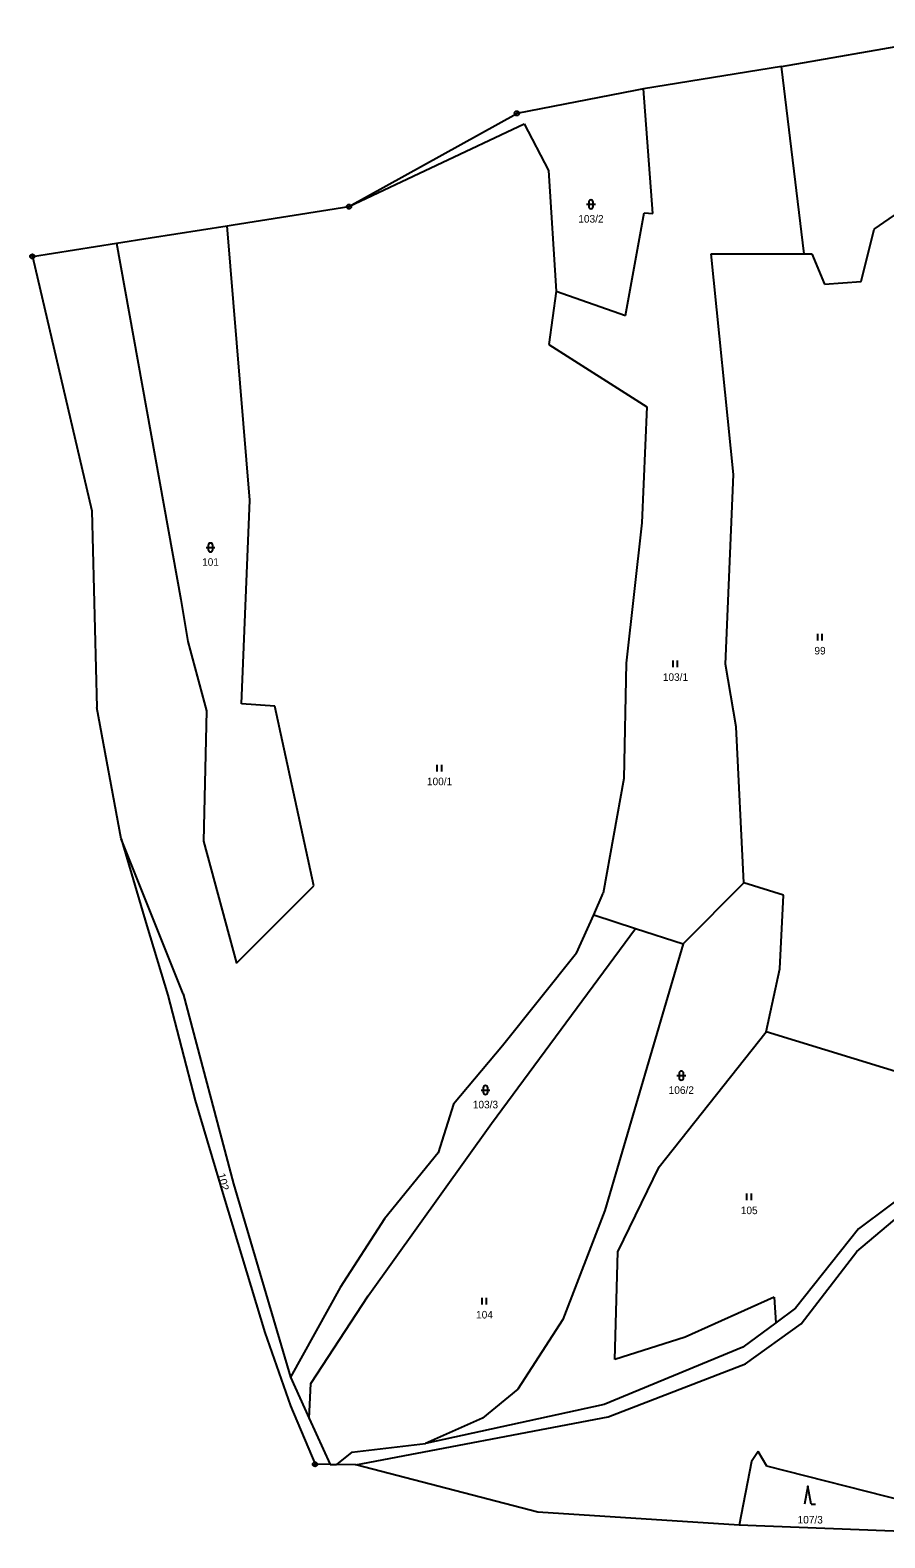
# Model space of a CAD drawing. Extents: x -601877 to -599786, y -1122905 to -1121218.
# Drawn here: x -601877.1 to -601684.6, y -1122131.2 to -1121791.7 of the extents above; entities that cross this region are included whole.
import ezdxf
from ezdxf.enums import TextEntityAlignment as Align

# ---------------------------------------------------------------- set-up
doc = ezdxf.new("R2010")
doc.units = 0
doc.header["$LTSCALE"] = 0.68
for name, color, linetype, lineweight in [('1', 7, 'Continuous', 25), ('3', 7, 'Continuous', 25), ('8', 7, 'Continuous', 25)]:
    doc.layers.add(name, color=color, linetype=linetype, lineweight=lineweight)
doc.layers.add('2', color=7, linetype='Continuous')

msp = doc.modelspace()

# ---------------------------------------------------------------- linework, layer by layer
at = {"layer": '1'}
for p, q in [((-601707.88, -1121799.89), (-601660.68, -1121791.7)), ((-601707.88, -1121799.89), (-601738.97, -1121804.94)), ((-601702.78, -1121842.1), (-601707.88, -1121799.89)), ((-601740.83, -1121805.3), (-601767.46, -1121810.44)), ((-601738.97, -1121804.94), (-601740.83, -1121805.3)), ((-601736.8, -1121832.96), (-601738.97, -1121804.94)), ((-601805.27, -1121831.44), (-601767.46, -1121810.44)), ((-601686.97, -1121836.54), (-601649.03, -1121810.29)), ((-601805.27, -1121831.44), (-601765.84, -1121812.82)), ((-601765.84, -1121812.82), (-601760.34, -1121823.28)), ((-601760.34, -1121823.28), (-601758.58, -1121850.46)), ((-601831.32, -1121835.53), (-601805.27, -1121831.44)), ((-601742.96, -1121855.97), (-601738.78, -1121832.85)), ((-601738.78, -1121832.85), (-601736.8, -1121832.96)), ((-601827.61, -1121897.52), (-601832.71, -1121835.75)), ((-601689.89, -1121848.32), (-601686.97, -1121836.54)), ((-601876.57, -1121842.65), (-601857.64, -1121839.67)), ((-601857.64, -1121839.67), (-601850.06, -1121838.48)), ((-601857.64, -1121839.67), (-601843.1, -1121919.91)), ((-601876.57, -1121842.65), (-601863.21, -1121899.96)), ((-601723.71, -1121842.04), (-601702.78, -1121842.1)), ((-601718.65, -1121891.74), (-601723.71, -1121842.04)), ((-601702.78, -1121842.1), (-601701, -1121842.1)), ((-601701, -1121842.1), (-601698.19, -1121848.92)), ((-601758.58, -1121850.46), (-601760.23, -1121862.46)), ((-601758.58, -1121850.46), (-601742.96, -1121855.97)), ((-601698.19, -1121848.92), (-601689.89, -1121848.32)), ((-601760.23, -1121862.46), (-601738.16, -1121876.51)), ((-601738.16, -1121876.51), (-601739.33, -1121902.63)), ((-601720.47, -1121934.44), (-601718.65, -1121891.74)), ((-601829.49, -1121943.36), (-601827.61, -1121897.52)), ((-601863.21, -1121899.96), (-601862.08, -1121944.21)), ((-601739.33, -1121902.63), (-601742.85, -1121934.22)), ((-601843.1, -1121919.91), (-601841.56, -1121929.38)), ((-601841.56, -1121929.38), (-601837.37, -1121944.96)), ((-601742.85, -1121934.22), (-601743.4, -1121960.2)), ((-601718.1, -1121948.58), (-601720.47, -1121934.44)), ((-601856.55, -1121973.77), (-601862.08, -1121944.21)), ((-601837.37, -1121944.96), (-601838.04, -1121974.28)), ((-601821.99, -1121943.91), (-601829.49, -1121943.36)), ((-601813.19, -1121984.41), (-601821.99, -1121943.91)), ((-601716.34, -1121983.69), (-601718.1, -1121948.58)), ((-601743.4, -1121960.2), (-601748.02, -1121986.06)), ((-601856.55, -1121973.77), (-601850.81, -1121993.37)), ((-601842.61, -1122008.73), (-601856.55, -1121973.77)), ((-601838.04, -1121974.28), (-601830.56, -1122001.8)), ((-601716.34, -1121983.69), (-601729.98, -1121997.44)), ((-601707.43, -1121986.5), (-601716.34, -1121983.69)), ((-601830.56, -1122001.8), (-601813.19, -1121984.41)), ((-601750.15, -1121990.88), (-601748.02, -1121986.06)), ((-601708.2, -1122003.06), (-601707.43, -1121986.5)), ((-601850.81, -1121993.37), (-601846.05, -1122009.01)), ((-601773.2, -1122037.89), (-601740.72, -1121993.95)), ((-601753.99, -1121999.56), (-601750.15, -1121990.88)), ((-601750.15, -1121990.88), (-601740.72, -1121993.95)), ((-601740.72, -1121993.95), (-601729.98, -1121997.44)), ((-601729.98, -1121997.44), (-601747.63, -1122057.49)), ((-601753.99, -1121999.56), (-601770.68, -1122020.4)), ((-601711.28, -1122017.26), (-601708.2, -1122003.06)), ((-601846.05, -1122009.01), (-601839.92, -1122032.73)), ((-601842.61, -1122008.73), (-601831.31, -1122051.47)), ((-601735.42, -1122047.64), (-601711.28, -1122017.26)), ((-601678.29, -1122027.39), (-601711.28, -1122017.26)), ((-601770.68, -1122020.4), (-601781.75, -1122033.55)), ((-601839.92, -1122032.73), (-601833.45, -1122054.42)), ((-601781.75, -1122033.55), (-601785.19, -1122044.46)), ((-601800.94, -1122076.69), (-601773.2, -1122037.89)), ((-601655.82, -1122035.62), (-601690.54, -1122061.59)), ((-601785.19, -1122044.46), (-601797.26, -1122059.37)), ((-601744.72, -1122066.79), (-601735.42, -1122047.64)), ((-601831.31, -1122051.47), (-601818.46, -1122095)), ((-601833.45, -1122054.42), (-601824.22, -1122084.95)), ((-601747.63, -1122057.49), (-601757.09, -1122081.99)), ((-601690.9, -1122066.7), (-601679.9, -1122057.48)), ((-601797.26, -1122059.37), (-601807.26, -1122074.84)), ((-601690.54, -1122061.59), (-601704.68, -1122079.45)), ((-601745.42, -1122091.01), (-601744.72, -1122066.79)), ((-601703.41, -1122082.99), (-601690.9, -1122066.7)), ((-601807.26, -1122074.84), (-601818.46, -1122095)), ((-601813.83, -1122096.47), (-601800.94, -1122076.69)), ((-601709.52, -1122076.97), (-601729.54, -1122086)), ((-601709.52, -1122076.97), (-601709.12, -1122082.74)), ((-601757.09, -1122081.99), (-601767.2, -1122097.73)), ((-601704.68, -1122079.45), (-601709.12, -1122082.74)), ((-601824.22, -1122084.95), (-601818.46, -1122101.5)), ((-601709.12, -1122082.74), (-601716.56, -1122088.25)), ((-601715.95, -1122092.04), (-601703.41, -1122082.99)), ((-601716.56, -1122088.25), (-601747.78, -1122101.13)), ((-601729.54, -1122086), (-601745.42, -1122091.01)), ((-601746.86, -1122103.95), (-601715.95, -1122092.04)), ((-601818.46, -1122095), (-601814.23, -1122104.32)), ((-601814.23, -1122104.32), (-601813.83, -1122096.47)), ((-601767.2, -1122097.73), (-601775.18, -1122104.23)), ((-601818.46, -1122101.5), (-601812.91, -1122114.62)), ((-601747.78, -1122101.13), (-601788.03, -1122109.93)), ((-601814.23, -1122104.32), (-601809.53, -1122114.66)), ((-601803.71, -1122114.72), (-601746.86, -1122103.95)), ((-601775.18, -1122104.23), (-601788.03, -1122109.93)), ((-601804.65, -1122111.92), (-601808.04, -1122114.67)), ((-601804.65, -1122111.92), (-601788.03, -1122109.93)), ((-601713.14, -1122111.77), (-601714.6, -1122114.03)), ((-601711.13, -1122115.08), (-601713.14, -1122111.77)), ((-601809.53, -1122114.66), (-601812.91, -1122114.62)), ((-601809.53, -1122114.66), (-601808.04, -1122114.67)), ((-601803.71, -1122114.72), (-601808.04, -1122114.67)), ((-601762.75, -1122125.41), (-601803.71, -1122114.72)), ((-601714.6, -1122114.03), (-601717.39, -1122128.37)), ((-601679.83, -1122123.03), (-601711.13, -1122115.08)), ((-601717.39, -1122128.37), (-601762.75, -1122125.41)), ((-601643.19, -1122131.19), (-601717.39, -1122128.37))]:
    msp.add_line(p, q, dxfattribs=at)
msp.add_lwpolyline([(-601850.06, -1121838.48), (-601832.71, -1121835.75), (-601831.32, -1121835.53)], dxfattribs=at)
at = {"layer": '3'}
for p, q in [((-601751.771, -1121830.911), (-601749.769, -1121830.911)), ((-601751.271, -1121830.411), (-601751.271, -1121831.412)), ((-601750.269, -1121831.412), (-601750.269, -1121830.411)), ((-601837.451, -1121908.181), (-601835.449, -1121908.181)), ((-601836.951, -1121907.681), (-601836.951, -1121908.682)), ((-601835.949, -1121908.682), (-601835.949, -1121907.681)), ((-601699.691, -1121929.15), (-601699.691, -1121927.65)), ((-601698.69, -1121929.15), (-601698.69, -1121927.65)), ((-601732.251, -1121935.1), (-601732.251, -1121933.6)), ((-601731.25, -1121935.1), (-601731.25, -1121933.6)), ((-601785.371, -1121958.6), (-601785.371, -1121957.1)), ((-601784.37, -1121958.6), (-601784.37, -1121957.1)), ((-601731.421, -1122027.101), (-601729.419, -1122027.101)), ((-601730.921, -1122026.601), (-601730.921, -1122027.602)), ((-601729.919, -1122027.602), (-601729.919, -1122026.601)), ((-601775.531, -1122030.351), (-601773.529, -1122030.351)), ((-601775.031, -1122029.851), (-601775.031, -1122030.852)), ((-601774.029, -1122030.852), (-601774.029, -1122029.851)), ((-601715.641, -1122055.18), (-601715.641, -1122053.68)), ((-601714.64, -1122055.18), (-601714.64, -1122053.68)), ((-601775.261, -1122078.67), (-601775.261, -1122077.17)), ((-601774.26, -1122078.67), (-601774.26, -1122077.17)), ((-601701.2, -1122123.58), (-601700.204, -1122123.58))]:
    msp.add_line(p, q, dxfattribs=at)
msp.add_lwpolyline([(-601701.2, -1122123.58), (-601701.95, -1122119.58), (-601702.7, -1122123.58)], dxfattribs=at)
for centre, start, end in [((-601750.77, -1121830.4109), 0, 180), ((-601750.77, -1121831.4109), 180, 359.98789), ((-601836.45, -1121907.6809), 0, 180), ((-601836.45, -1121908.6809), 180, 359.98789), ((-601730.42, -1122026.6009), 0, 180), ((-601730.42, -1122027.6009), 180, 359.98789), ((-601774.53, -1122029.8509), 0, 180), ((-601774.53, -1122030.8509), 180, 359.98789)]:
    msp.add_arc(centre, 0.5, start, end, dxfattribs=at)
at = {"layer": '8'}
for centre, radius in [((-601767.46, -1121810.4399), 0.5), ((-601767.46, -1121810.4399), 0.0303), ((-601805.27, -1121831.4399), 0.5), ((-601805.27, -1121831.4399), 0.0303), ((-601876.57, -1121842.6499), 0.5), ((-601876.57, -1121842.6499), 0.0303), ((-601812.91, -1122114.6199), 0.5), ((-601812.91, -1122114.6199), 0.0303)]:
    msp.add_circle(centre, radius, dxfattribs=at)

# ---------------------------------------------------------------- texts
at = {"layer": '2'}
for s, p in [('103/2', (-601750.77, -1121835.035)), ('101', (-601836.449, -1121912.305)), ('99', (-601699.179, -1121932.275)), ('103/1', (-601731.74, -1121938.225)), ('100/1', (-601784.86, -1121961.725)), ('106/2', (-601730.42, -1122031.225)), ('103/3', (-601774.53, -1122034.475)), ('105', (-601715.129, -1122058.305)), ('104', (-601774.749, -1122081.795)), ('107/3', (-601701.39, -1122127.955))]:
    msp.add_text(s, height=1.7, dxfattribs=at).set_placement(p, align=Align.CENTER)
at = {"layer": '2', "width": 1.05}
msp.add_text('102', height=1.7, rotation=284, dxfattribs=at).set_placement((-601834.3753, -1122051.2179), align=Align.CENTER)

doc.saveas('drawing.dxf')
